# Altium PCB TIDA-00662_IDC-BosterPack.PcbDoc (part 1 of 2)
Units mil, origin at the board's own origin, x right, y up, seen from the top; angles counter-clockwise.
Board outline 2854.33 x 3248.03 mil, 4 copper layers (Top Layer, GND, +3.3V_Supply, Bottom Layer), stack 35.6 mil thick; 124 components, 110 nets, 427 pads, 203 vias.
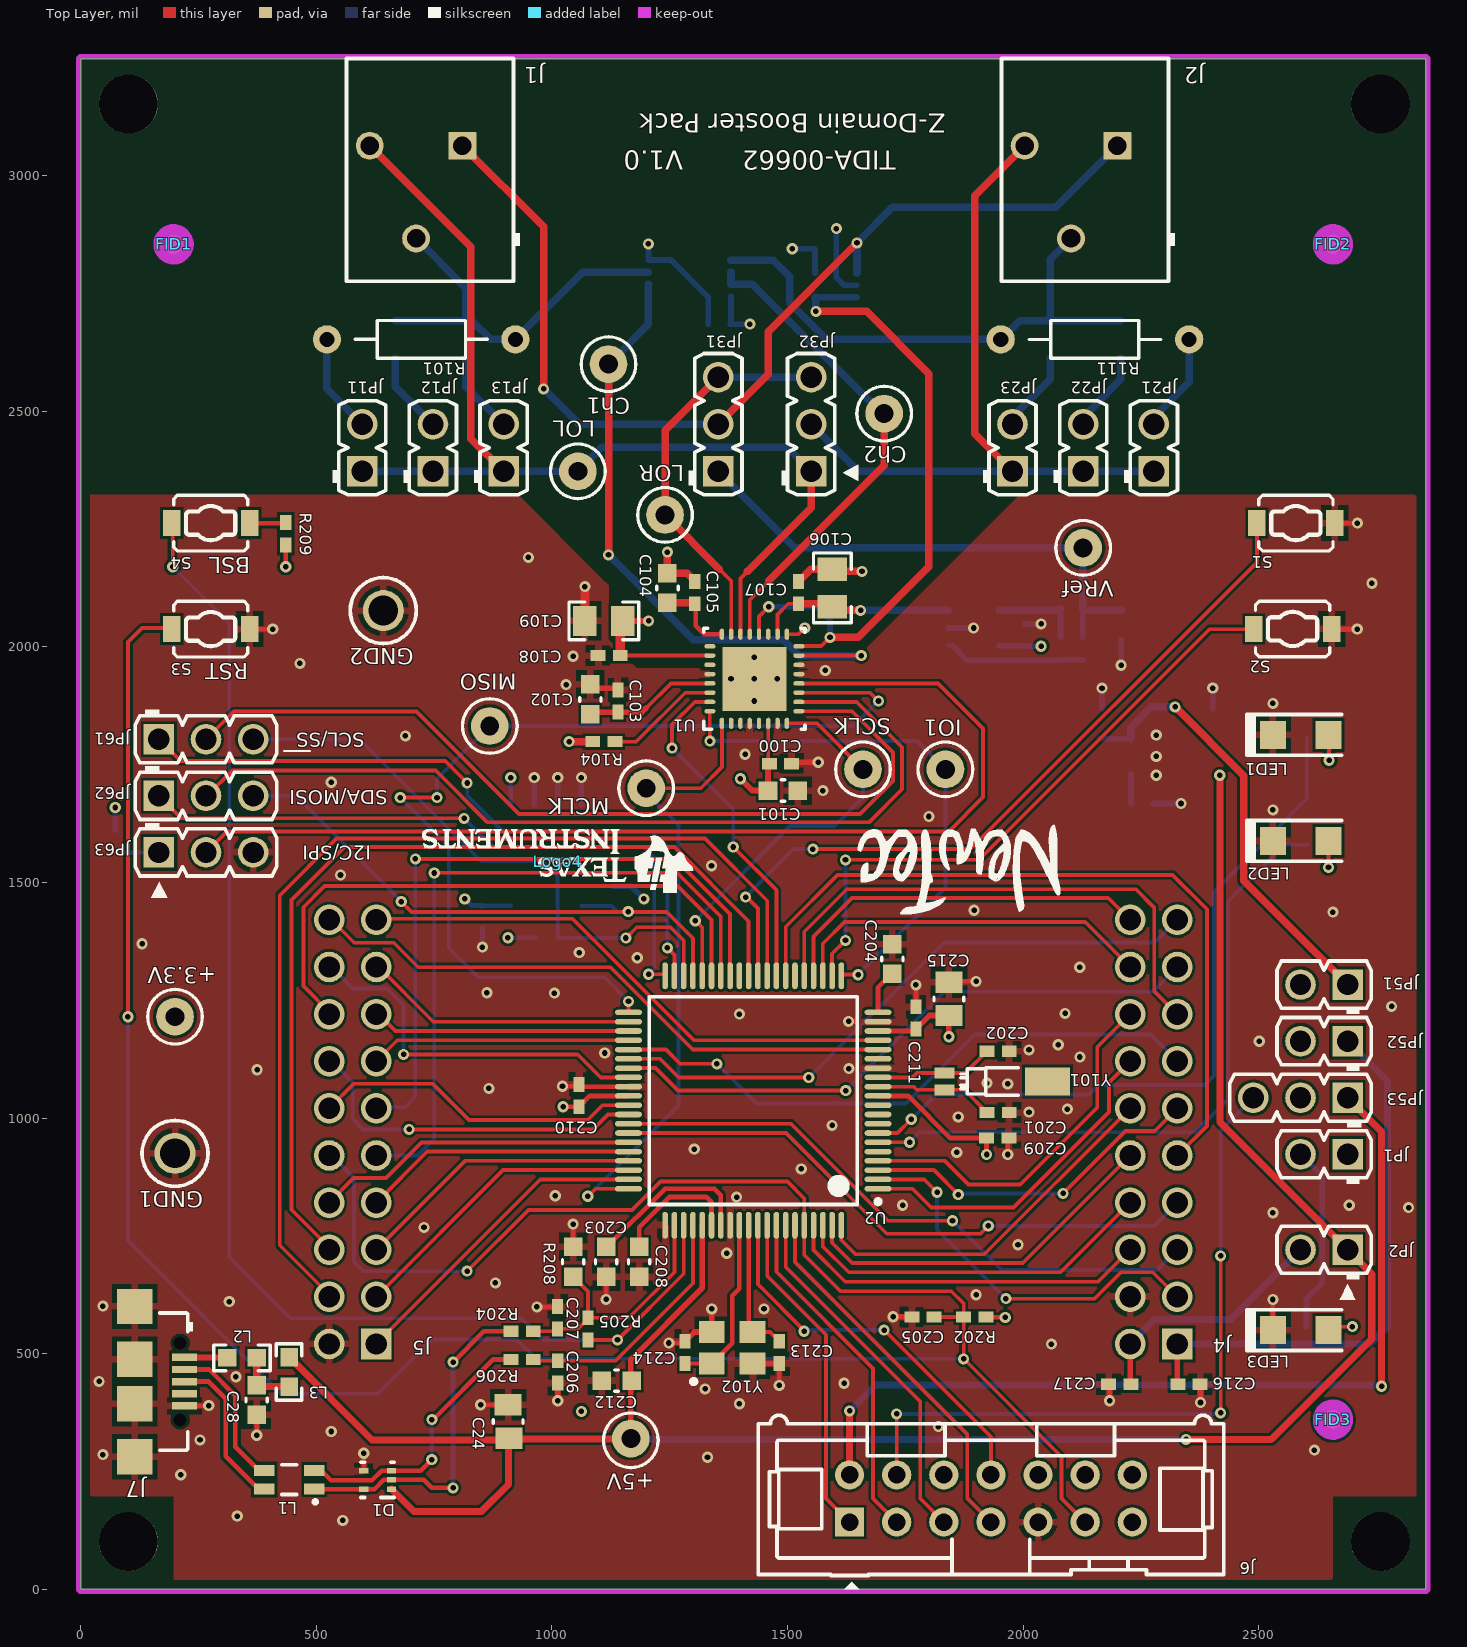
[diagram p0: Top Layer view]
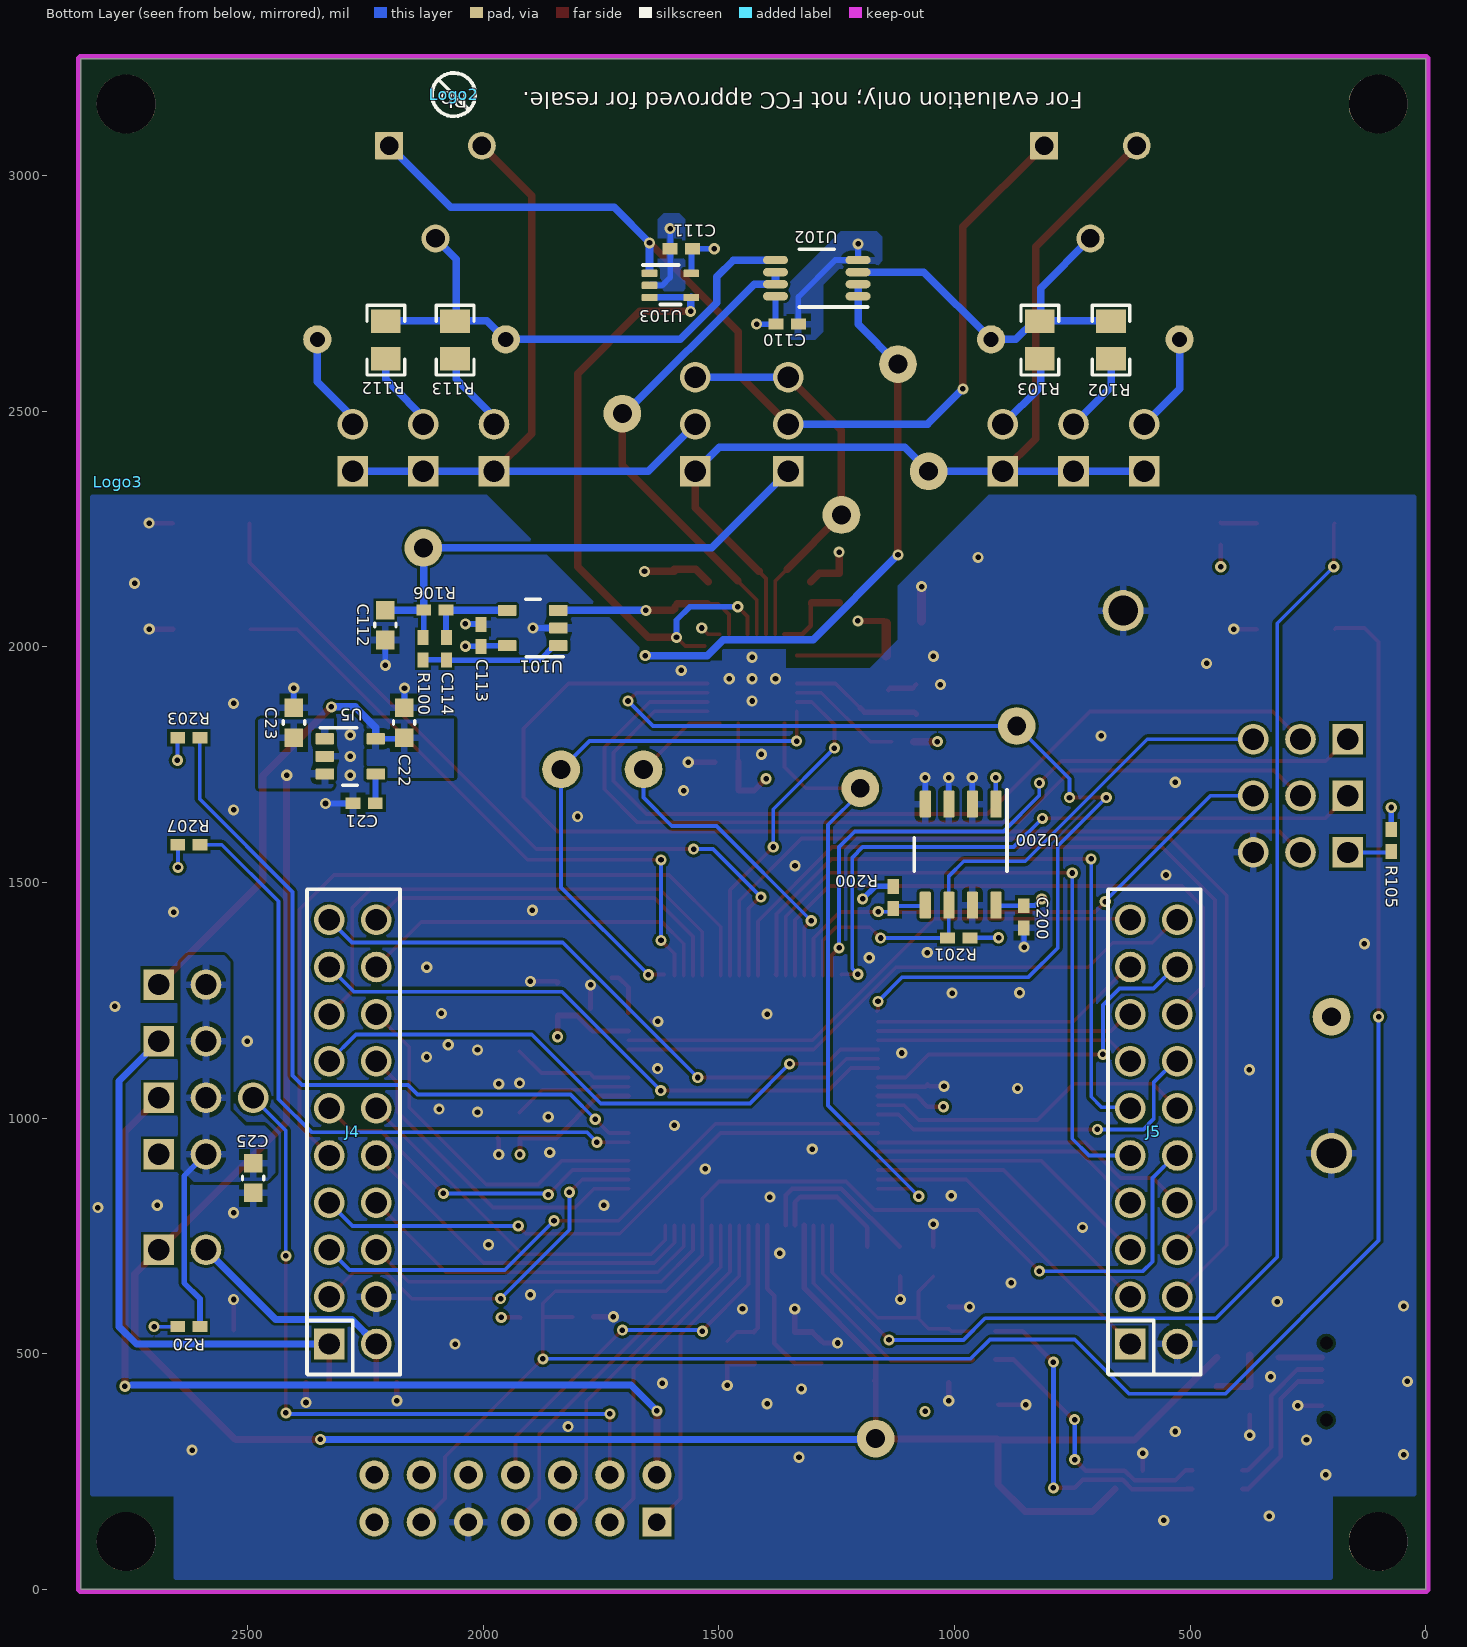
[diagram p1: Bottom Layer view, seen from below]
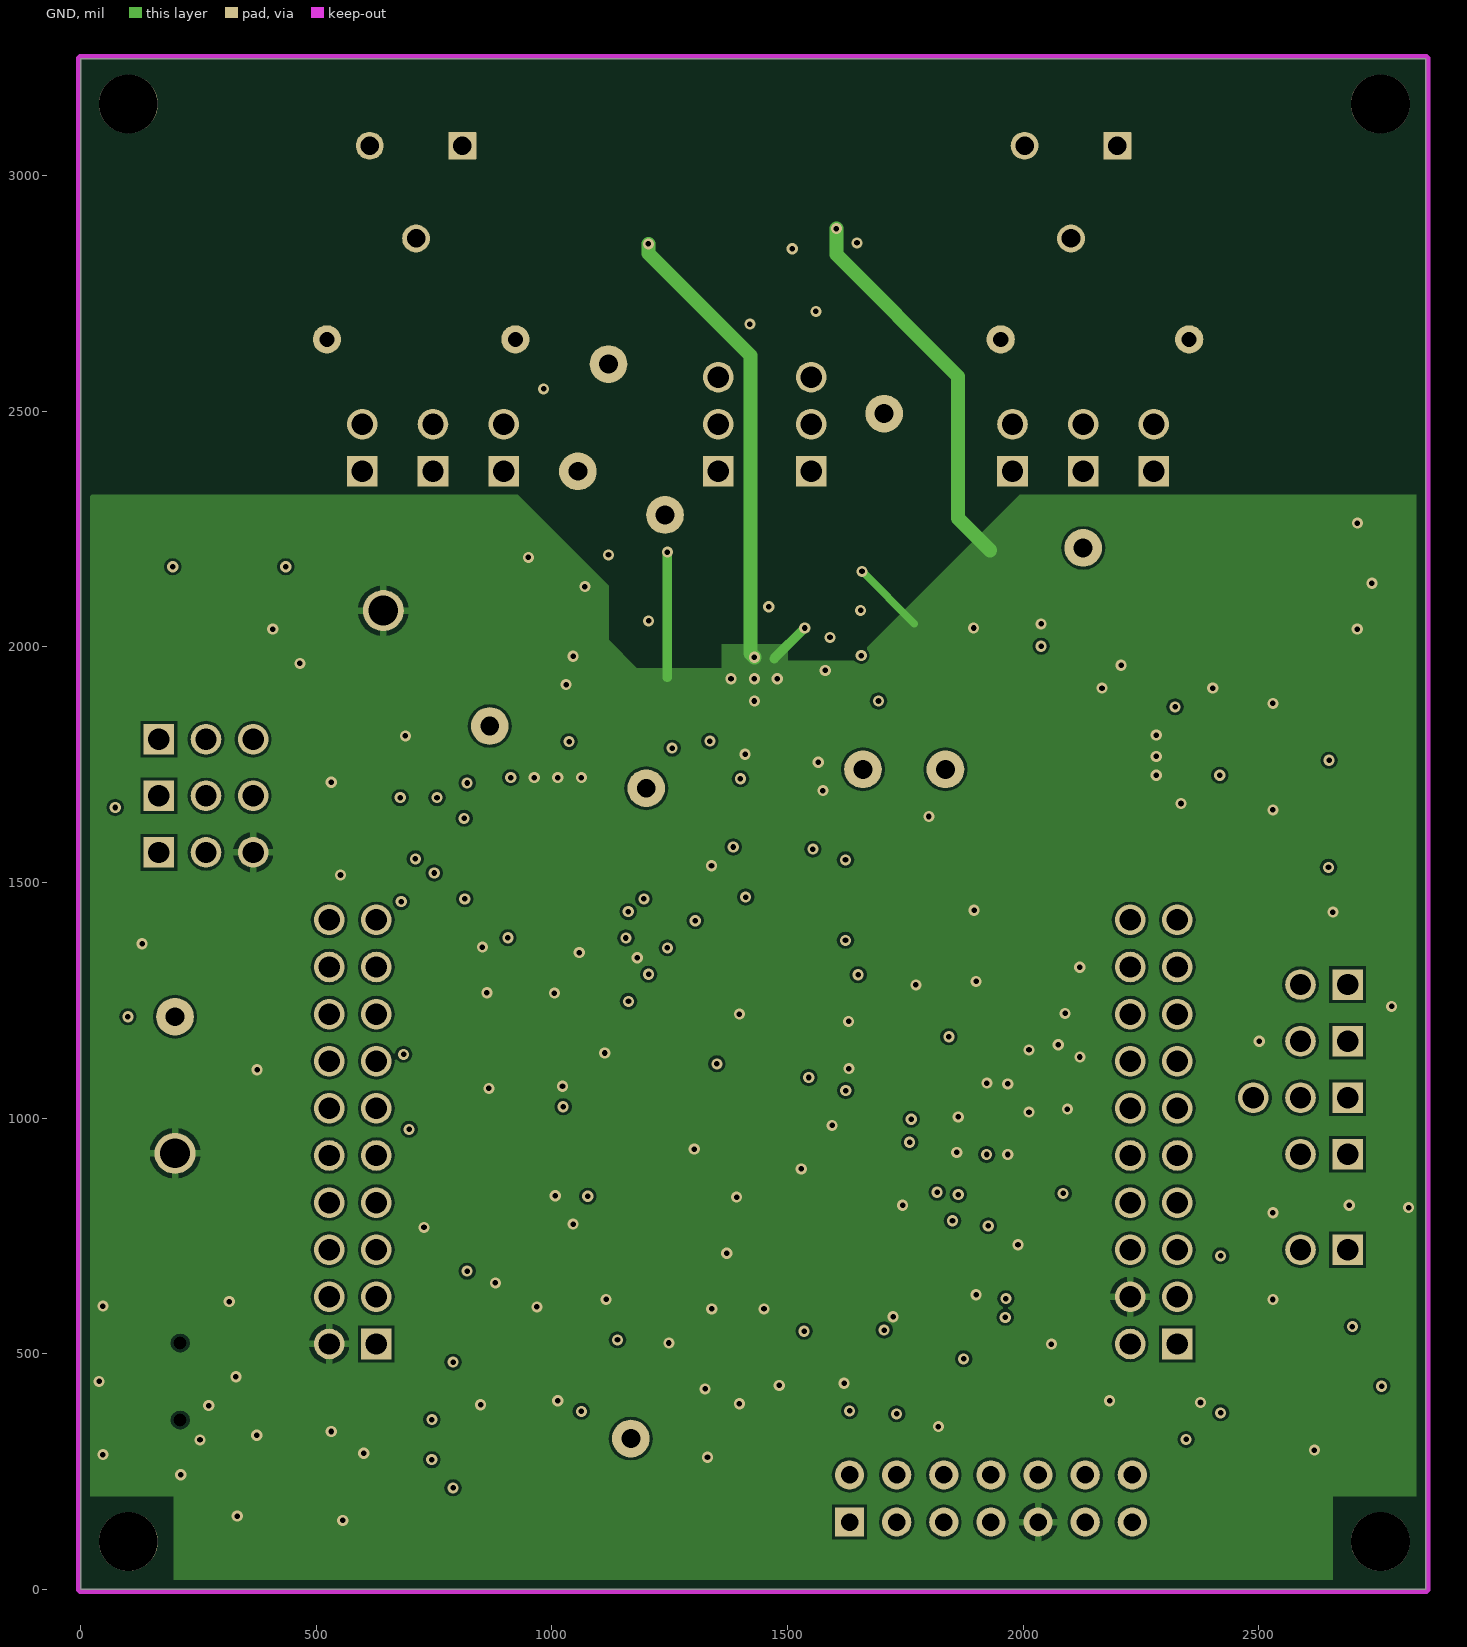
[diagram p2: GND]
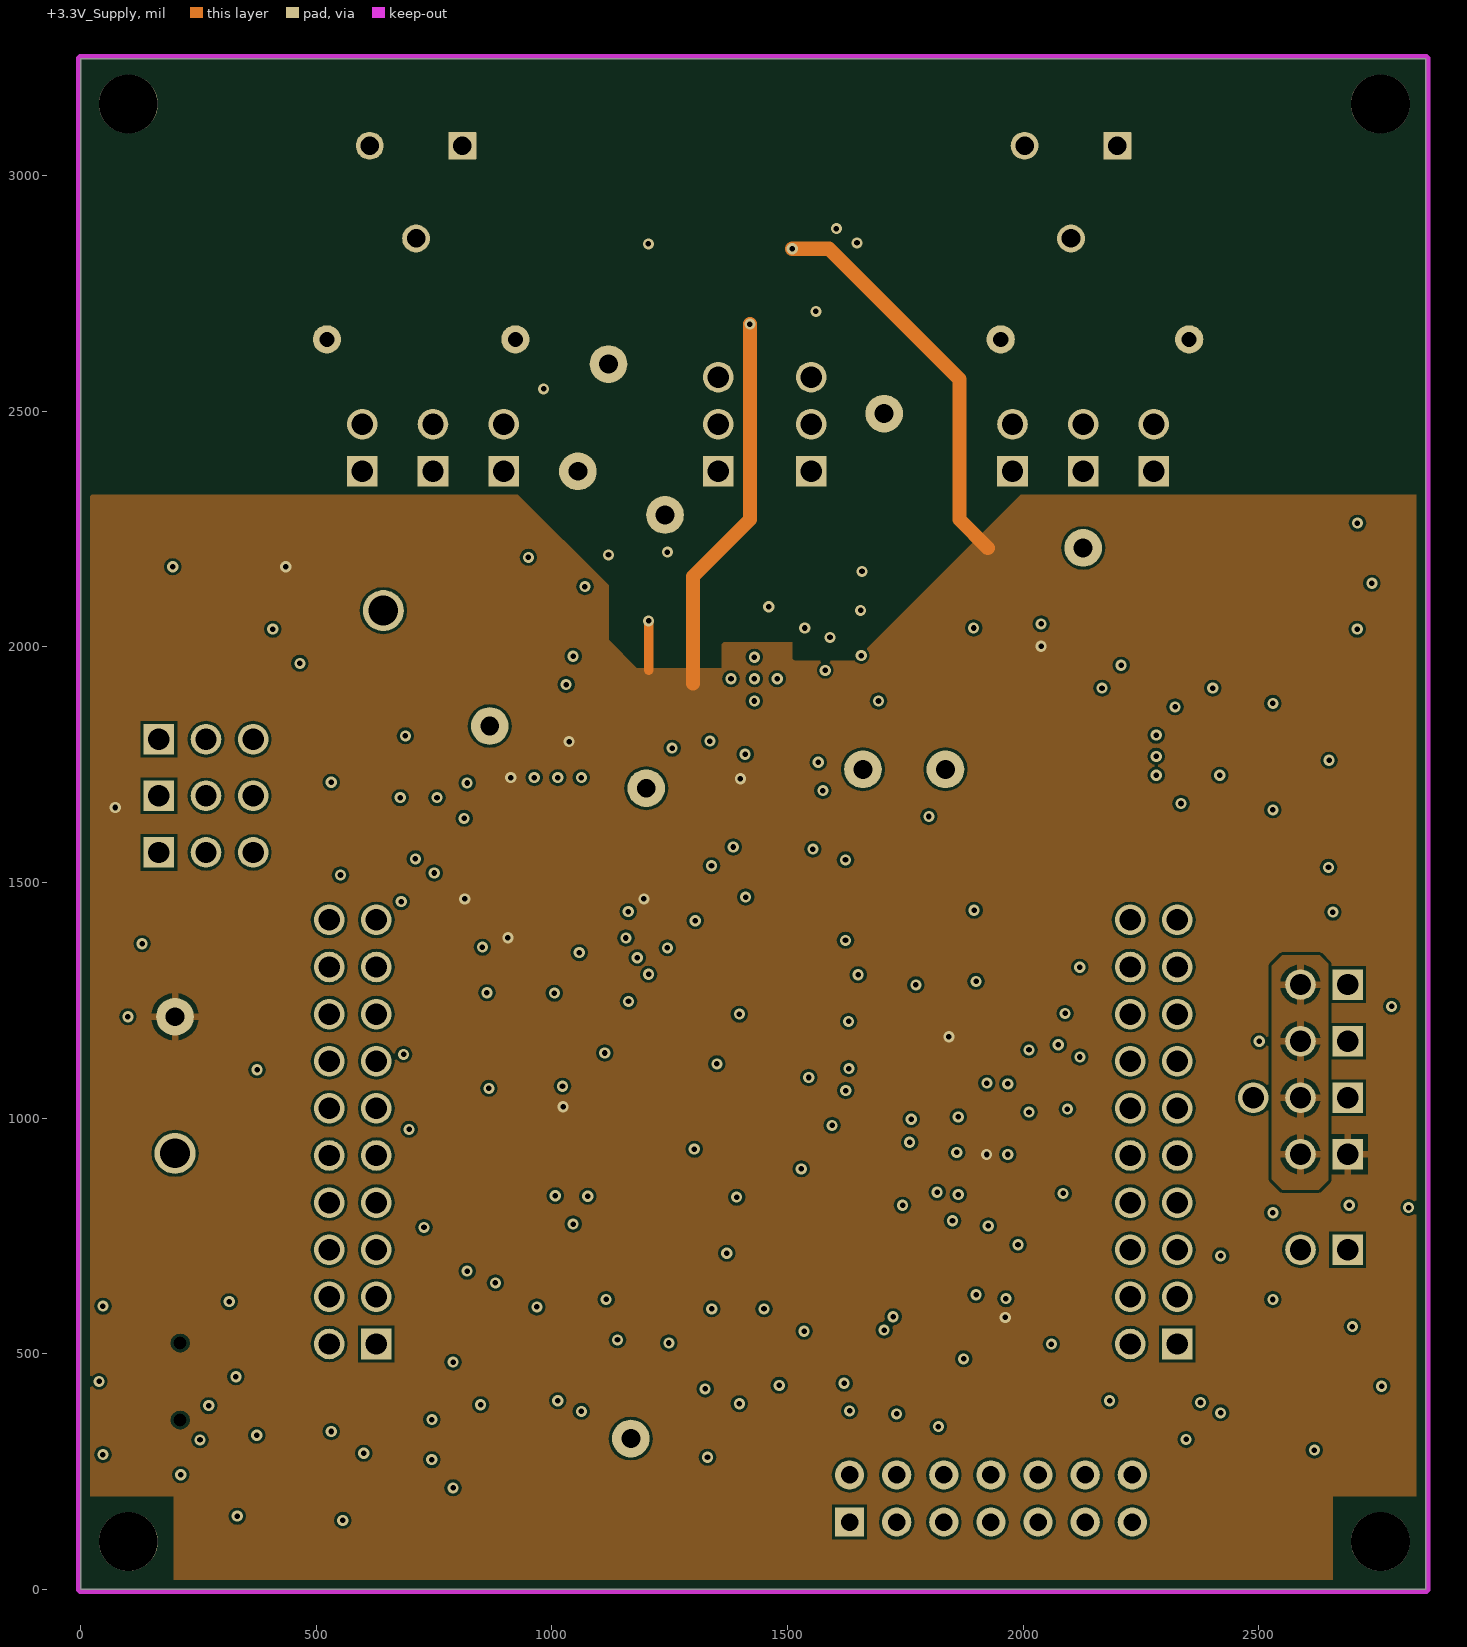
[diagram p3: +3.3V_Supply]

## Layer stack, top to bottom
Top Solder: solder mask 0.4, Solder Resist, Dk 3.5
Top Layer: signal copper 1.4
Dielectric1: prepreg 5, FR-4, Dk 4.2
Dielectric 6: prepreg 5, FR-4, Dk 4.2
GND: signal copper 1.4
Dielectric3: prepreg 5, FR-4, Dk 4.2
Dielectric5: prepreg 5, FR-4, Dk 4.2
+3.3V_Supply: signal copper 1.4
Dielectric4: prepreg 5, FR-4, Dk 4.2
Dielectric 8: prepreg 5, FR-4, Dk 4.2
Bottom Layer: signal copper 1.4
Bottom Solder: solder mask 0.4, Solder Resist, Dk 3.5

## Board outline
0,0 2854.33,0 2854.33,3248.03 0,3248.03

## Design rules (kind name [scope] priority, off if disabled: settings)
Clearance [All] p1: gap=6
DiffPairsRouting [All] p1: maxlimit=393.7 minlimit=4.92 mostfreqgap=5.91 toplayer_minwidth=15 toplayer_maxwidth=15 toplayer_prefwidth=15 midlayer2_minwidth=15 midlayer2_maxwidth=15 midlayer2_prefwidth=15 midlayer3_minwidth=15 midlayer3_maxwidth=15 midlayer3_prefwidth=15 bottomlayer_minwidth=15 bottomlayer_maxwidth=15 bottomlayer_prefwidth=15 maxuncoupledlength=500
FabricationTestPointUsage FabricationTestPointUsage_1 [All] p1: valid=0 allowmultiple=FALSE
FabricationTestpoint FabricationTestpoint_1 [All] p1: side=3 testpointundercomponent=TRUE minsize=40 maxsize=100 preferedsize=60 minholesize=0 maxholesize=40 preferedholesize=32 testpointgrid=1 allowsidetop=TRUE allowsidebottom=TRUE usegrid=TRUE gridtolerance=0.01
HoleSize [All] p1: absolutevalues=TRUE maxlimit=236.22 minlimit=7.87 maxpercent=80.000 minpercent=20.000
HoleSize FabricationTestpoint [All] p2 off: absolutevalues=TRUE maxlimit=100 minlimit=1 maxpercent=80.000 minpercent=20.000
HoleSize FabricationTestPointUsage [All] p3 off: absolutevalues=TRUE maxlimit=100 minlimit=1 maxpercent=80.000 minpercent=20.000
MinimumSolderMaskSliver MinimumSolderMaskSliverTPD2E001 [HasFootprint('DRL0005A') vs HasFootprint('DRL0005A')] p1: minsoldermaskwidth=1.77
MinimumSolderMaskSliver MinimumSolderMaskSliverOPA2376 [HasFootprint('DGK0008A_N') vs HasFootprint('DGK0008A_N')] p2: minsoldermaskwidth=1
MinimumSolderMaskSliver MinimumSolderMaskSliver_MSP [HasFootprint('PN0080A_N') vs HasFootprint('PN0080A_N')] p3: minsoldermaskwidth=1
MinimumSolderMaskSliver [All] p4: minsoldermaskwidth=2
PlaneClearance [All] p1: clearance=19.68
PlaneConnect [All] p1: planeconnectstyle=Relief reliefexpansion=15.75 reliefentries=4 reliefconductorwidth=5.91 reliefairgap=5.91
PolygonConnect ViaConnect [IsVia] p1: connectstyle=Direct reliefconductorwidth=10 reliefentries=4 polygonreliefangle="90 Angle" airgapwidth=10
PolygonConnect [All] p2: connectstyle=Relief reliefconductorwidth=15 reliefentries=4 polygonreliefangle="90 Angle" airgapwidth=10
RoutingCorners [All] p1: cornerstyle=45-Degree minsetback=49.21 maxsetback=49.21
RoutingVias [All] p1: holewidth=11.81 width=23.62 viastyle="Through Hole" minholewidth=3.94 minwidth=9.84 maxholewidth=17.72 maxwidth=29.53
SilkToSilkClearance SilkToSilkClearance_Pb-free [(HasFootprint('Pb-Free_Overlay_Medium') OR HasFootprint('Pb-Free_Overlay_Small')) vs (HasFootprint('Pb-Free_Overlay_Medium') OR HasFootprint('Pb-Free_Overlay_Small'))] p1: silktosilkclearance=0
SilkToSilkClearance [All] p2: silktosilkclearance=3
SilkToSolderMaskClearance [IsPad] p1: minsilkscreentomaskgap=1 clearancetoexposedcopper=FALSE
SolderMaskExpansion [All] p1: expansion=2.95
Width [All] p1: maxlimit=393.7 minlimit=3 preferedwidth=5.91
20 further rules are at their usual default settings.

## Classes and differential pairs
component class AssemblyNote: ZZ2 ZZ3 ZZ4
component class FiducialMark: FID1 FID2 FID3
component class TIDA-00662_TID_Hardware: FID1 FID2 FID3 Logo2 Logo3 Logo4 ZZ2 ZZ3 ZZ4
component class Logo: Logo4
component class Header: J6 JP1 JP2 JP11 JP12 JP13 JP21 JP22 JP23 JP31 JP32 JP51 JP52 JP53 JP61 JP62 JP63
component class TIDA-00662_AIC3254: C100 C101 C102 C103 C104 C105 C106 C107 C108 C109 C110 C111 C112 C113 C114 Ch1 Ch2 IO1 J J1 J2 JP11 JP12 JP13 JP21 JP22 JP23 JP31 JP32 JP61 JP62 JP63 LOL LOR MCLK MISO R100 R101 R102 R103 R104 R105 R106 R111 R112 R113 SCLK U1 U101 U102 U103 VRef
component class TIDA-00662_ExternalInterfaces: C28 C216 C217 D1 J J4 J5 J6 J7 L1 L2 L3
component class TIDA-00662_MCU: C200 C201 C202 C203 C204 C205 C206 C207 C208 C209 C210 C211 C212 C213 C214 C215 LED1 LED2 R200 R201 R202 R203 R204 R205 R206 R207 R208 R209 S1 S2 S3 S4 U2 U200 Y101 Y102
component class TIDA-00662_PowerSupply: +3.3V +5V C21 C22 C23 C24 C25 GND1 GND2 JP1 JP2 JP51 JP52 JP53 LED3 R20 U5

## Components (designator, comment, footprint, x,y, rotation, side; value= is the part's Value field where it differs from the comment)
+3.3V "5000" Keystone5000#1 200,1215 r90 top
+5V "5000" Keystone5000#2 1167.37,316 r90 top
C21 "10nF" 0402W 2253,1668 r0 bottom
C22 "0.1uF" 0603_095 2168,1839 r270 bottom
C23 "0.1uF" 0603_095 2402,1839 r270 bottom
C24 "4.7uF" 0805_145#1 907,356 r90 top
C25 "0.1uF" 0603_095 2488.58,872.5 r90 bottom
C28 "680nF" 0603_095 373.3,401.7 r90 top
C100 "0.1uF" 0402W 1485,1752 r180 top
C101 "1uF" 0603_095 1490,1695 r180 top
C102 "1uF" 0603_095 1081.3,1888.7 r270 top
C103 "0.1uF" 0402W 1140,1885 r270 top
C104 "1uF" 0603_095 1245,2125 r270 top
C105 "0.1uF" 0402W 1302.87,2115 r270 top
C106 "1uF" 0805_HV 1595,2125 r270 top
C107 "0.1uF" 0402W 1523,2115 r90 top
C108 "0.1uF" 0402W 1121.38,1981.5 r0 top
C109 "2.2uF" 0805_HV 1110,2055 r180 top
C110 "0.1uF" 0402W 1355,2685 r180 bottom
C111 "0.1uF" 0402W 1580,2845 r0 bottom
C112 "1uF" 0603_095 2208,2046 r90 bottom
C113 "0.1uF" 0402W 2005,2024 r90 bottom
C114 "47nF" 0402W 2078,1996 r270 bottom
C200 "0.1uF" 0402W 853,1427 r90 bottom
C201 "15pF" 0402W 1946.74,1011.58 r0 top
C202 "15pF" 0402W 1946.74,1141.58 r0 top
C203 "0.22uF" 0603_095 1115,695 r90 top
C204 "470nF" 0603_095 1722.37,1337.52 r270 top
C205 "2200pF" 0402W 1787.37,577.52 r180 top
C206 "10pF" 0402W 1012.37,461.14 r270 top
C207 "10pF" 0402W 1011.58,576.14 r90 top
C208 "0.22uF" 0603_095 1185,695 r90 top
C209 "0.1uF" 0402W 1945.99,957.52 r0 top
C210 "0.1uF" 0402W 1057.37,1047.52 r90 top
C211 "0.1uF" 0402W 1772.37,1212.52 r90 top
C212 "0.22uF" 0603_095 1137.37,442.52 r0 top
C213 "33pF" 0402W 1482.37,502.52 r270 top
C214 "33pF" 0402W 1282.37,502.52 r270 top
C215 "4.7uF" 0805_145#2 1842.37,1252.95 r90 top
C216 "0.1uF" 0402W 2352,435 r180 top
C217 "0.1uF" 0402W 2205,435 r0 top
Ch1 "5002" Keystone5002 1120,2600 r90 top
Ch2 "5002" Keystone5002 1705,2495 r90 top
D1 "TPD2E001DRLR" DRL0005A 630,232 r180 top
FID1 "Fiducial" Fiducial10-20 196.85,2854.33 r90 top
FID2 "Fiducial" Fiducial10-20 2657.48,2854.33 r90 top
FID3 "Fiducial" Fiducial10-20 2657.48,360 r90 top
GND1 "5011" Keystone5011 200,925 r90 top
GND2 "5011" Keystone5011 642,2077 r90 top
IO1 "5002" Keystone5002 1835,1740 r90 top
J1 "1990012" Phoenix_1990012 711.58,2965.16 r180 top
J2 "1990012" Phoenix_1990012 2101.57,2965.16 r180 top
J4 "SSW-110-23-F-D" CONN_SSW-110-23-F-D 2277.17,970.47 r270 bottom
J5 "SSW-110-23-F-D" CONN_SSW-110-23-F-D 577.17,970.47 r270 bottom
J6 "N2514-6002-RB" 3M_x2514-60xx 1931.58,192.52 r0 top
J7 "629105136821" Wurth_629105136821 57.46,440.69 r270 top
JP1 "61300211121" WURTH_61300211121 2638.58,922.99 r180 top
JP2 "61300211121" WURTH_61300211121 2638.58,720.47 r180 top
JP11 "61300211121" WURTH_61300211121 597.37,2422.52 r90 top
JP12 "61300211121" WURTH_61300211121 747.37,2422.52 r90 top
JP13 "61300211121" WURTH_61300211121 897.37,2422.52 r90 top
JP21 "61300211121" WURTH_61300211121 2277.37,2422.52 r90 top
JP22 "61300211121" WURTH_61300211121 2127.37,2422.52 r90 top
JP23 "61300211121" WURTH_61300211121 1977.37,2422.52 r90 top
JP31 "61300311121" WURTH_61300311121 1353.16,2472.52 r90 top
JP32 "61300311121" WURTH_61300311121 1550.01,2472.52 r90 top
JP51 "61300211121" WURTH_61300211121 2638.58,1283.23 r180 top
JP52 "61300211121" WURTH_61300211121 2638.58,1163.15 r180 top
JP53 "61300311121" WURTH_61300311121 2588.58,1043.07 r180 top
JP61 "61300311121" WURTH_61300311121 265.75,1803.86 r0 top
JP62 "61300311121" WURTH_61300311121 265.75,1683.78 r0 top
JP63 "61300311121" WURTH_61300311121 265.75,1563.7 r0 top
L1 "744232090" WE-CNSW_1206 442.37,232.52 r180 top
L2 "742792651" 0603 342,491 r0 top
L3 "742792651" 0603 442,461 r90 top
LED1 "150120RS75000" WL_SMCW_RED_1206 2588.94,1813 r0 top
LED2 "150120RS75000" WL_SMCW_RED_1206 2588.94,1588 r0 top
LED3 "150120RS75000" WL_SMCW_RED_1206 2588.95,550 r0 top
Logo2 "Pb-Free Symbol" Pb-Free_Overlay_Small 2063,3172 r0 bottom
Logo3 "FCC disclaimer" FCC_disclaimer 2776.01,2349 r270 bottom
Logo4 "Texas Instruments" TI_Stacked_Overlay_Small_Vertical 1012,1544 r90 top
LOL "5002" Keystone5002 1055,2372.52 r90 top
LOR "5002" Keystone5002 1240,2280 r90 top
MCLK "5002" Keystone5002 1200,1700 r90 top
MISO "5002" Keystone5002 868,1832 r90 top
R20 "1.00k" 0402W 2625,557.19 r0 bottom
R100 "51" 0402W 2128,1996 r270 bottom
R101 "150k" CMF50 722.37,2652.52 r180 top
R102 "100k" 0805_HV 668,2651 r270 bottom
R103 "200k" 0805_HV 819,2651 r270 bottom
R104 "4.7k" 0402W 1110,1798.79 r0 top
R105 "4.7k" 0402W 73,1589 r270 bottom
R106 "2.00k" 0402W 2103,2078 r180 bottom
R111 "150k" CMF50 2152.37,2652.52 r0 top
R112 "100k" 0805_HV 2207,2651 r270 bottom
R113 "200k" 0805_HV 2060,2651 r270 bottom
R200 "2.7k" 0402W 1130,1468 r90 bottom
R201 "2.7k" 0402W 991,1382 r180 bottom
R202 "47k" 0402W 1897.37,577.52 r0 top
R203 "1.00k" 0402W 2625,1807 r180 bottom
R204 "27" 0402W 936.58,547.52 r180 top
R205 "1.40k" 0402W 1076.58,552.52 r90 top
R206 "27" 0402W 936.58,487.52 r180 top
R207 "1.00k" 0402W 2625,1580 r180 bottom
R208 "1.00Meg" 0603_095 1045,695 r270 top
R209 "100" 0402W 435,2240 r270 top
S1 "TL1015AF160QG" SW_TL1015AF160QG 2578.74,2262.52 r0 top
S2 "TL1015AF160QG" SW_TL1015AF160QG 2572,2038 r180 top
S3 "RST" SW_TL1015AF160QG 275.59,2037.52 r0 top
S4 "BSL" SW_TL1015AF160QG 275.59,2262.52 r0 top
SCLK "5002" Keystone5002 1660,1740 r90 top
U1 "TLV320AIC3254IRHB" RHB0032E_NV 1429.54,1932.28 r90 top
U2 "MSP430F5529IPN" PN0080A_N 1427.17,1037.05 r180 top
U5 "TPS73633DBV" DBV0005A_N 2282.37,1767.52 r180 bottom
U101 "OPA317IDBV" DBV0005A_N 1895,2040 r0 bottom
U102 "OPA2376AIDGKR" DGK0008A_N 1292.37,2782.52 r0 bottom
U103 "OPA376AIDCKR" DCK0005A_N 1603,2767 r180 bottom
U200 "24FC1025T-I/SN" SOIC-8 987,1559 r270 bottom
VRef "5002" Keystone5002 2127.37,2210 r90 top
Y101 "MS3V-T1R 32.768KHZ +/-20PPM 12.5PF" XTAL_MS3V-T1R 1942.41,1077.56 r0 top
Y102 "7M-12.000MAAJ-T" TXC_7M 1382.37,512.52 r90 top
ZZ2 "These assemblies are ESD sensitive, ESD precautions shall be observed." AssemblyNote 185,3829.11 r0 top
ZZ3 "These assemblies must be clean and free from flux and all contaminants. Use of no clean flux is not acceptable." AssemblyNote 185,3740.56 r0 top
ZZ4 "These assemblies must comply with workmanship standards IPC-A-610 Class 2, unless otherwise specified." AssemblyNote 185,3652 r0 top

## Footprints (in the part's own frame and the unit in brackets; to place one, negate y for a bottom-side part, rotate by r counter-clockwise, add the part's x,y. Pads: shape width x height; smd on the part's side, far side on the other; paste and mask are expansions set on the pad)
3M_x2514-60xx [mil] "3M"
  rect 62x62 hole 37 paste+2: 1(-300,-50)
  round 62 hole 37: 2(-300,50) 3(-200,-50) 4(-200,50) 5(-100,-50) 6(-100,50) 7(0,-50) 8(0,50) 9(100,-50) 10(100,50) 11(200,-50) 12(200,50) 13(300,-50) 14(300,50)
  silkscreen extent -494,-193 494,177, body extent -494,-161 494,179, height 390
0402W [mm] "without printed body shape"
  rect 0.8x0.6 smd: 1(-0.6,0) 2(0.6,0)
  body extent -0.55,-0.3 0.55,0.3, height 0.6
0603 [mm] "0603 from SM-752 data"
  rect 1x0.95 smd: 1(-0.8,0) 2(0.8,0)
  silkscreen extent -1.52,-0.69 1.52,0.69, body extent -0.87,-0.47 0.87,0.47, height 1
0603_095 [mm] "0603_095"
  rect 1x1 smd: 1(-0.8,0) 2(0.8,0)
  silkscreen extent -0.1,-0.58 0.1,0.58, body extent -0.87,-0.48 0.87,0.48, height 0.95
0805_145#1 [mm] "0805 / 1.45mm height"
  rect 1.15x1.45 smd: 1(-0.9,-0.052) 2(0.9,0)
  silkscreen extent -0.1,-0.8 0.1,0.8, body extent -1.1,-0.72 1.1,0.72, height 1.45
0805_145#2 [mm] "0805 / 1.45mm height"
  rect 1.15x1.45 smd: 1(-0.9,0) 2(0.9,0)
  silkscreen extent -0.1,-0.8 0.1,0.8, body extent -1.1,-0.72 1.1,0.72, height 1.45
0805_HV [mil] "0805 with 30mil clearance between pads"
  rect 50x63 smd: 1(-40,0) 2(40,0)
  silkscreen extent -74,-40 74,40, body extent -43,-29 43,29, height 57
AssemblyNote [mil] "Assembly Note"
CMF50 [mil] "VIshay Metal Film Resistors 1/4W"
  round 60 hole 32: 1(-200,0) 2(200,0)
  silkscreen extent -140,-40 140,40, body extent -214,-40 214,40, height 80
CONN_SSW-110-23-F-D [mm] "SAMTEC"
  rect 1.65x1.65 hole 1.15: 1(11.43,-1.27)
  round 1.65 hole 1.15: 2(11.43,1.27) 3(8.89,-1.27) 4(8.89,1.27) 5(6.35,-1.27) 6(6.35,1.27) 7(3.81,-1.27) 8(3.81,1.27) 9(1.27,-1.27) 10(1.27,1.27) 11(-1.27,-1.27) 12(-1.27,1.27) 13(-3.81,-1.27) 14(-3.81,1.27) 15(-6.35,-1.27) 16(-6.35,1.27) 17(-8.89,-1.27) 18(-8.89,1.27) 19(-11.43,-1.27) 20(-11.43,1.27)
  silkscreen extent -13.08,-2.46 13.08,2.54, body extent -13,-2.51 13,2.54, height 8.59
DBV0005A_N [mm] "SOT23, 5-Leads, Body 2.9x1.6mm, Pitch 0.95mm, Lead Span 2.8mm, IPC Medium Density"
  rrect17% 1x0.6 smd: 1(-1.375,0.95) 2(-1.375,0) 3(-1.375,-0.95) 4(1.375,-0.95) 5(1.375,0.95)
  silkscreen extent -1.63,-1.55 0.38,1.55, body extent -1.42,-1.46 1.42,1.46, height 1.09
DCK0005A_N [mm] "SOT353, 5-Leads, Body 2x1.3mm, Pitch 0.65mm, Lead Span 2.1mm, IPC Medium Density"
  rrect25% 0.85x0.4 smd: 1(-1.125,0.65) 2(-1.125,0) 3(-1.125,-0.65) 4(1.125,-0.65) 5(1.125,0.65)
  silkscreen extent -1.48,-1.02 0.55,1.1, body extent -1.14,-1 1.14,1, height 0.95
DGK0008A_N [mm] "TSOP, 8-Leads, Body 3x3mm, Pitch 0.65mm, IPC Medium Density"
  oval 1.35x0.45 smd: 1(-2.225,0.975) 2(-2.225,0.325) 3(-2.225,-0.325) 4(-2.225,-0.975) 5(2.225,-0.975) 6(2.225,-0.325) 7(2.225,0.325) 8(2.225,0.975)
  silkscreen extent -2.75,-1.55 0.95,1.55, body extent -2.45,-1.5 2.45,1.5, height 0.96
DRL0005A [mm] "SOTFL, 5-Flat Leads, Body 1.2x1.6x0.6mm, Pitch 0.5mm, TI recommended"
  rect 0.5x0.3 smd: 1(-0.75,0.5) 2(-0.75,0) 3(-0.75,-0.5) 4(0.75,-0.5) 5(0.75,0.5)
  silkscreen extent -0.9,-0.95 0.9,0.95, body extent -0.85,-0.85 0.85,0.85, height 0.62
FCC_disclaimer [mil]
Fiducial10-20 [mm]
  round 1 smd mask+0.5: 1(0,0)
  Top Layer keep-out circle w1.178: c0,0 r0.5
Keystone5000#1 [mil] "For Keystone 500x miniature loop terminals"
  round 80 hole 40: 1(0,0)
  silkscreen extent -58,-58 58,58, body extent -49,-49 49,49, height 182
Keystone5000#2 [mil] "For Keystone 500x miniature loop terminals"
  round 80 hole 40: 1(3.62,0)
  silkscreen extent -58,-58 58,58, body extent -49,-49 49,49, height 182
Keystone5002 [mil] "For Keystone 500x miniature loop terminals"
  round 80 hole 40: 1(0,0)
  silkscreen extent -58,-58 58,58, body extent -49,-49 49,49, height 182
Keystone5011 [mil] "Keystone Multipurpose loops"
  round 87 hole 63: 1(0,0)
  silkscreen extent -70,-70 70,70, body extent -63,-63 63,62, height 319
Pb-Free_Overlay_Small [mil]
  silkscreen extent -46,-46 46,46
Phoenix_1990012 [mm] "Terminal Block, 2.5mm, 3 Pos, TH"
  rrect7% 1.5x1.5 hole 1: 1(-2.5,-2.5)
  round 1.5 hole 1: 2(0,2.5) 3(2.5,-2.5)
  silkscreen extent -5.6,-7.2 3.75,4.8, body extent -5.25,-7.2 3.75,4.8, height 13.11
PN0080A_N [mm] "QFP, 80-Leads, Body 12x12mm, Pitch 0.5mm, IPC Medium Density"
  oval 1.45x0.3 smd: 1(-6.725,4.75) 2(-6.725,4.25) 3(-6.725,3.75) 4(-6.725,3.25) 5(-6.725,2.75) 6(-6.725,2.25) 7(-6.725,1.75) 8(-6.725,1.25) 9(-6.725,0.75) 10(-6.725,0.25) 11(-6.725,-0.25) 12(-6.725,-0.75) 13(-6.725,-1.25) 14(-6.725,-1.75) 15(-6.725,-2.25) 16(-6.725,-2.75) 17(-6.725,-3.25) 18(-6.725,-3.75) 19(-6.725,-4.25) 20(-6.725,-4.75) 41(6.725,-4.75) 42(6.725,-4.25) 43(6.725,-3.75) 44(6.725,-3.25) 45(6.725,-2.75) 46(6.725,-2.25) 47(6.725,-1.75) 48(6.725,-1.25) 49(6.725,-0.75) 50(6.725,-0.25) 51(6.725,0.25) 52(6.725,0.75) 53(6.725,1.25) 54(6.725,1.75) 55(6.725,2.25) 56(6.725,2.75) 57(6.725,3.25) 58(6.725,3.75) 59(6.725,4.25) 60(6.725,4.75)
  oval 0.3x1.45 smd: 21(-4.75,-6.725) 22(-4.25,-6.725) 23(-3.75,-6.725) 24(-3.25,-6.725) 25(-2.75,-6.725) 26(-2.25,-6.725) 27(-1.75,-6.725) 28(-1.25,-6.725) 29(-0.75,-6.725) 30(-0.25,-6.725) 31(0.25,-6.725) 32(0.75,-6.725) 33(1.25,-6.725) 34(1.75,-6.725) 35(2.25,-6.725) 36(2.75,-6.725) 37(3.25,-6.725) 38(3.75,-6.725) 39(4.25,-6.725) 40(4.75,-6.725) 61(4.75,6.725) 62(4.25,6.725) 63(3.75,6.725) 64(3.25,6.725) 65(2.75,6.725) 66(2.25,6.725) 67(1.75,6.725) 68(1.25,6.725) 69(0.75,6.725) 70(0.25,6.725) 71(-0.25,6.725) 72(-0.75,6.725) 73(-1.25,6.725) 74(-1.75,6.725) 75(-2.25,6.725) 76(-2.75,6.725) 77(-3.25,6.725) 78(-3.75,6.725) 79(-4.25,6.725) 80(-4.75,6.725)
  silkscreen extent -6.85,-5.6 5.6,5.6, body extent -7,-7 7,7, height 1.56
RHB0032E_NV [mm] "QFN, 32-Leads, Body 5x5mm, Pitch 0.5mm, Thermal Pad 3.45x3.45mm, TI Recommended"
  oval 0.6x0.24 smd: 1(-2.4,1.75) 2(-2.4,1.25) 3(-2.4,0.75) 4(-2.4,0.25) 5(-2.4,-0.25) 6(-2.4,-0.75) 7(-2.4,-1.25) 8(-2.4,-1.75) 17(2.4,-1.75) 18(2.4,-1.25) 19(2.4,-0.75) 20(2.4,-0.25) 21(2.4,0.25) 22(2.4,0.75) 23(2.4,1.25) 24(2.4,1.75)
  oval 0.24x0.6 smd: 9(-1.75,-2.4) 10(-1.25,-2.4) 11(-0.75,-2.4) 12(-0.25,-2.4) 13(0.25,-2.4) 14(0.75,-2.4) 15(1.25,-2.4) 16(1.75,-2.4) 25(1.75,2.4) 26(1.25,2.4) 27(0.75,2.4) 28(0.25,2.4) 29(-0.25,2.4) 30(-0.75,2.4) 31(-1.25,2.4) 32(-1.75,2.4)
  rect 3.45x3.45 smd paste-1.725: 33(0,0)
  silkscreen extent -2.72,-2.73 2.72,2.73, body extent -2.57,-2.57 2.58,2.58, height 1.01
SOIC-8 [mm] "duplicate of SO-8.  SOIC, 8-Leads, Body 5.0x4.0mm (max), Pitch 1.27mm, IPC Medium Density"
  rrect17% 1.45x0.6 smd: 1(-2.725,1.905) 2(-2.725,0.635) 3(-2.725,-0.635) 4(-2.725,-1.905) 5(2.725,-1.905) 6(2.725,-0.635) 7(2.725,0.635) 8(2.725,1.905)
  silkscreen extent -3.5,-2.5 0.9,2.5, body extent -3,-2.45 3,2.45, height 1.63
SW_TL1015AF160QG [mm] "E-Switch"
  rect 0.95x1.4 smd: 1(-2.1,0) 2(2.1,0)
  silkscreen extent -2,-1.5 2,1.5, body extent -2.3,-1.5 2.3,1.5, height 2
TI_Stacked_Overlay_Small_Vertical [mil]
  silkscreen extent -66,-288 69,288
TXC_7M [mm] "TXC"
  rect 1.2x1.4 smd: 1(-0.85,1.1) 2(-0.85,-1.1) 3(0.85,-1.1) 4(0.85,1.1)
  silkscreen extent -1.95,1.95 -1.7,2.2, body extent -1.3,-1.65 1.3,1.65, height 0.8
WE-CNSW_1206 [mm] "SMD, 4-Leads, Body 3.2x1.6mm"
  rect 1.1x0.6 smd: 1(-1.35,0.5) 2(1.35,0.5) 3(1.35,-0.5) 4(-1.35,-0.5)
  silkscreen extent -1.5,-0.8 0.4,1.3, body extent -1.6,-0.8 1.6,0.8, height 1.91
WL_SMCW_RED_1206 [mm] "SMD, 2-Leads, Body 3.2x1.6mm, Pitch 3mm"
  rect 1.4x1.5 smd: 1(-1.5,0) 2(1.5,0)
  silkscreen extent -2.9,-1.1 2.2,1.1, body extent -1.6,-0.85 1.6,0.85, height 0.78
WURTH_61300211121 [mm] "Header, 2.54mm, 2x1, TH"
  rect 1.65x1.65 hole 1.15: 1(-1.27,0)
  round 1.65 hole 1.15: 2(1.27,0)
  silkscreen extent -2.54,-1.27 2.54,1.6, body extent -2.54,-1.27 2.54,1.27, height 8.54
WURTH_61300311121 [mm] "Header, 2.54mm, 3x1, TH"
  rect 1.65x1.65 hole 1.15: 1(-2.54,0)
  round 1.65 hole 1.15: 2(0,0) 3(2.54,0)
  silkscreen extent -3.81,-1.27 3.81,1.6, body extent -3.81,-1.27 3.81,1.27, height 8.54
Wurth_629105136821 [mm] "USB 2.0 TYPE B, R/A, SMT"
  rect 0.4x1.35 smd: 1(-1.3,4.125) 2(-0.65,4.125) 3(0,4.125) 4(0.65,4.125) 5(1.3,4.125)
  rect 1.9x1.9 smd: 6(-4.05,1.45) 7(-1.2,1.45) 8(1.2,1.45) 9(4.05,1.45)
  round 0 hole 0.7 unplated: MH1(-2.075,3.9) MH2(2.075,3.9)
  silkscreen extent -3.7,2.8 3.7,4.6, body extent -4,-1.3 4,4.6, height 2.7
XTAL_MS3V-T1R [mm] "Micro Crystal Switzerland recommended land pattern"
  rect 1.1x0.6 smd: 1(-2.775,0.45) 2(-2.775,-0.45)
  rect 2.4x1.5 smd: ""(2.775,0)
  silkscreen extent -1.9,-0.74 1.2,0.74, body extent -3.05,-0.74 3.65,0.74, height 1.42

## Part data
+3.3V +5V: "Test Point, Miniature, Red, TH"
C21: library part 885012205031, "CAP, CERM, 0.01 µF, 16 V, +/- 10%, X7R, 0402"
C22 C23 C25: library part 885012206046, "CAP, CERM, 0.1 µF, 16 V, +/- 10%, X7R, 0603_095"
C24 C215: library part 885012207025, "CAP, CERM, 4.7 µF, 10 V, +/- 10%, X7R, 0805"
C28: library part 885012206051, "CAP, CERM, 680 nF, 16V, +/- 10%, X7R, 0603_095"
C100 C103 C105 C107 C108 C110 C111 C113 C200 C209 C210 C211 C216 C217: library part 885012205037, "CAP, CERM, 0.1 µF, 16 V, +/- 10%, X7R, 0402"
C101 C102 C104 C112: library part 885012206052, "CAP, CERM, 1 µF, 16 V, +/- 10%, X7R, 0603_095"
C106: library part 08055C105KAT2A, "CAP, CERM, 1 µF, 50 V, +/- 10%, X7R, 0805"
C109: library part 0805YD225KAT2A, "CAP, CERM, 2.2 µF, 16 V, +/- 10%, X5R, 0805"
C114: library part 885012205035, "CAP, CERM, 47 nF, 16 V, +/- 10%, X7R 0402"
C201 C202: library part 885012005056, "CAP, CERM, 15 pF, 50 V, +/- 5%, C0G/NP0, 0402"
C203 C208 C212: library part 885012206048, "CAP, CERM, 0.22 µF, 16 V, +/- 10%, X7R, 0603_095"
C204: library part 885012206050, "CAP, CERM, 470 nF, 16 V, +/- 10%, X7R, 0603_095"
C205: library part 885012205027, "CAP, CERM, 2200 pF, 16 V, +/- 10%, X7R, 0402"
C206 C207: library part 885012005025, "CAP, CERM, 10 pF, 16 V, +/- 5%, C0G/NP0, 0402"
C213 C214: library part 885012005043, "CAP, CERM, 33 pF, 25 V, +/- 5%, C0G/NP0, 0402"
Ch1 Ch2 IO1 LOL LOR MCLK MISO SCLK VRef: "Test Point, Miniature, White, TH"
D1: "Low-Capacitance + / - 15 kV ESD-Protection Array for High-Speed Data Interfaces, 2 Channels, -40 to +85 degC, 5-pin SOT (DRL), Green (RoHS & no Sb/Br)"
FID1 FID2 FID3: "Fiducial mark.  There is nothing to buy or mount."
GND1 GND2: "Test Point, Multipurpose, Black, TH"
J1 J2: "Terminal Block, 2.5mm, 3 Pos, TH"
J4 J5: "Connector, Receptacle, 100mil, 10x2, Gold plated, TH"
J6: "Header (shrouded), 100mil, 7x2, Gold, TH"
J7: "USB 2.0 TYPE B, R/A, SMT"
JP1 JP2 JP11 JP12 JP13 JP21 JP22 JP23 JP51 JP52: "Header, 2.54 mm, 2x1, Gold, TH"
JP31 JP32 JP53 JP61 JP62 JP63: "Header, 2.54 mm, 3x1, Gold, TH"
L1: "Coupled inductor,  A, 0.3 ohm, +/- 25%, SMD"
L2 L3: "Ferrite Bead, 600 ohm @ 100 MHz, 1 A, 0603"
LED1 LED2 LED3: "LED, Red, SMD"
Logo2: library part Pb-Free
Logo3: library part FCC_disclaimer, "FCC_disclaimer"
Logo4: library part TI_Logo, "Texas Instrument Corporate Signature"
R20 R203 R207: library part CRCW04021K00FKED, "RES, 1.00 k, 1%, 0.063 W, 0402"
R100: library part CRCW040251R0JNED, "RES, 51, 5%, 0.063 W, 0402"
R101 R111: library part CMF50150K00FHEB, "RES, 150 k, 1%, 0.25 W, TH"
R102 R112: library part CRCW0805100KFKEA, "RES, 100 k, 1%, 0.125 W, 0805"
R103 R113: library part CRCW0805200KFKEA, "RES, 200 k, 1%, 0.125 W, 0805"
R104 R105: library part CRCW04024K70JNED, "RES, 4.7 k, 5%, 0.063 W, 0402"
R106: library part CRCW04022K00FKED, "RES, 2.00 k, 1%, 0.063 W, 0402"
R200 R201: library part CRCW04022K70JNED, "RES, 2.7 k, 5%, 0.063 W, 0402"
R202: library part CRCW040247K0JNED, "RES, 47 k, 5%, 0.063 W, 0402"
R204 R206: library part CRCW040227R0JNED, "RES, 27, 5%, 0.063 W, 0402"
R205: library part CRCW04021K40FKED, "RES, 1.40 k, 1%, 0.063 W, 0402"
R208: library part CRCW06031M00FKEA, "RES, 1.00 M, 1%, 0.1 W, 0603"
R209: library part CRCW0402100RFKED, "RES, 100, 1%, 0.063 W, 0402"
S1 S2: "Switch, Tactile, SPST-NO, 0.05A, 12V, SMT"
S3 S4: library part TL1015AF160QG, "Switch, Tactile, SPST-NO, 0.05A, 12V, SMT"
U1: "Ultra Low Power Stereo Audio Codec With Embedded miniDSP, RHB0032E"
U2: "25 MHz Mixed Signal Microcontroller with 128 KB Flash, 8192 B SRAM and 63 GPIOs, -40 to 85 degC, 80-pin QFP (PN), Green (RoHS & no Sb/Br)"
U5: "Cap-Free, NMOS, 400mA Low-Dropout Regulator with Reverse Current Protection, DBV0005A"
U101: "Low-Offset, Rail-to-Rail I/O Operational Amplifier, DBV0005A"
U102: "Precision, Low Noise, Low Quiescent Current Operational Amplifier, 2 to 5.5 V, -40 to 125 degC, 8-pin SOP (DGK0008A), Green (RoHS & no Sb/Br)"
U103: "Precision, Low Noise, Low Iq Operational Amplifier, 2.2 to 5.5 V, -40 to 125 degC, 5-pin SOT23 (DCK0005A), Green (RoHS & no Sb/Br)"
U200: "IC, EEPROM, 512kB, 1MHz, SOIC-8"
Y101: "Crystal, 32.768kHz, 12.5pF, SMD"
Y102: "Crystal, 12.000MHz, 18pF, SMD"
ZZ2 ZZ3 ZZ4: library part AssemblyNote

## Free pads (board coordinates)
  round 125 hole 125 unplated: 1(100.8,100.94) 2(2758.28,100.94) 3(100.8,3152.13) 4(2758.28,3152.13)

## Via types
v1: diameter 23.62, hole 11.81, Top Layer to Bottom Layer, 200 vias
v2: diameter 23.62, hole 11.81, Top Layer to Bottom Layer, tented top, 2 vias
v3: diameter 23.62, hole 11.81, Top Layer to Bottom Layer, tented bottom, 1 vias

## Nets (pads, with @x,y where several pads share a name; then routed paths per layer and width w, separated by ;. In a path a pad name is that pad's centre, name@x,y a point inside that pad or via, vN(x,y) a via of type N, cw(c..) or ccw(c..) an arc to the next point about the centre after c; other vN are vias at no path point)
+3.3V_BP: C216.2 J4.1 JP52.1 | length 1185.9
  Top Layer w12: J4.1@2327.17,520.47 2327.16,439.5 C216.2@2329.14,437.52
  Bottom Layer w15: J4.1@2327.17,520.47 2736.5,520.47 2773,556.97 2773,1078.73 JP52.1@2688.58,1163.15
+3.3V_JTAG: J6.2 JP53.1 | length 1931.1
  Top Layer w15: J6.2@1631.58,242.52 v1(1631.58,378.42) ; JP53.1@2688.58,1043.07 2760.85,970.8 v1(2760.85,430.85)
  Bottom Layer w8: 2746.56,433.33 2758.37,433.33 v1(2760.85,430.85)
  Bottom Layer w15: v1(1631.58,378.42) 1686.5,433.33 2746.56,433.33
+3.3V_LDO: C22.2 JP51.1 U5.5 | length 944.9
  Top Layer w16: v1(2322.37,1872.52) 2468,1726.89 2468,1503.81 JP51.1@2688.58,1283.23 ; JP51.1@2689.77,1284.41 JP51.1@2690.95,1283.23
  Bottom Layer w12: C22.2@2163.47,1804.92 C22.2@2168.47,1804.92 ; C22.2@2167.37,1806.02 C22.2@2168.47,1804.92 ; U5.5@2228.24,1804.92 C22.2@2168.47,1804.92
  Bottom Layer w16: U5.5@2228.24,1804.92 2228.24,1828.39 2272.37,1872.52 v1(2322.37,1872.52)
+3.3V_SUPPLY: +3.3V.1 C100.2 C101.2 C108.2 C109.1 C110.1 C111.1 C113.1 C200.2 C209.1 C210.1 C211.1 C215.1 JP1.1 R104.1 R105.1 R200.2 R201.2 R202.2 R209.2 U1.6 U1.26 U2.11 U2.18 U2.50 U101.5 U102.8 U103.5 U200.1 U200.8 | length 3730.8
  Top Layer w8: C108.2@1145,1981.5 U1.26@1335.05,1981.5 ; C100.2@1459.06,1757.31 U1.6@1459.06,1837.8
  Top Layer w10: v1(435,2170) R209.2@435,2216.38 ; v1(1023.75,1023.9) C210.1@1057.37,1023.9 1080.36,1046.89 U2.50@1162.4,1046.89 ; U2.11@1691.93,1046.89 1756,1046.89 1845.37,957.52 C209.1@1922.37,957.52 v1(1922.37,922.52) ; U2.18@1691.93,1184.69 1768.16,1184.69 C211.1@1772.37,1188.9 ; R202.2@1921.54,575.87 1922.68,577 v1@1959,577
  Top Layer w12: C109.1@1145,2050 C109.1@1150,2055 v1(1205,2055) ; v1(1400,1720) 1425,1695 C101.2@1458.5,1695 1458.5,1756.76 C100.2@1459.06,1757.31 ; C211.1@1772.37,1188.9 1800.99,1217.52 C215.1@1842.37,1217.52 v1(1842.37,1172.52)
  Top Layer w16: v1(1036.21,1798.79) R104.1@1086.38,1798.79
  Top Layer w20: C108.2@1145,1981.5 C109.1@1145,2050
  +3.3V_Supply w20: 1205,1950 v1(1205,2055)
  +3.3V_Supply w30: 1299,1922.44 1299,2149 1420,2270 v1(1420,2685) ; v1(1510,2845) 1588,2845 1865,2568 1865,2270 1925,2210
  Bottom Layer w10: v3(814.89,1465) 828.75,1451.14 C200.2@852.37,1451.14 ; C200.2@852.37,1448.9 853.71,1450.24 U200.8@912.37,1450.24 ; v1(906.52,1382.52) R201.2@965.13,1382.52 ; U200.1@912.37,1664.8 v1(912.37,1722.52)
  Bottom Layer w12: R105.1@73,1610.62 v1(73,1659) ; R200.2@1130,1491.62 1168.38,1491.62 v1(1195,1465) ; U102.8@1379.97,2744.13 1379.97,2686.35 C110.1@1378.62,2685 v1(1420,2685) ; v1(1510,2845) C111.1@1556.38,2845 1558.08,2843.3 U103.5@1558.08,2793.11 ; U101.5@1949.13,2002.6 2003.78,2002.6 2005,2001.38 v1(2038,2001.38)
  other v1: 1962,577
+5V_BP: C217.2 J4.2 JP2.2 | length 526.9
  Top Layer w12: J4.2@2227.17,520.47 2227.16,436.46 C217.2@2228.62,435
  Bottom Layer w15: J4.2@2229.53,522.99 2279.06,572.52 2440.63,572.52 JP2.2@2588.58,720.47
+5V_USB: +5V.1 C23.2 C24.1 C212.2 D1.1 JP2.1 L3.2 U2.65 U5.1 U5.3 | length 4679.2
  Top Layer w12: +5V.1@1167.37,319 C212.2@1167.37,441.02 ; C212.2@1168.87,442.52 C212.2@1167.37,441.02 ; U2.65@1318.9,772.28 1318.9,639.05 1167.37,487.52 C212.2@1167.37,441.02
  Top Layer w15: L3.2@443.37,491.52 617.89,317 907.37,317 907.37,222.37 850,165 706.84,165 D1.1@659.53,212.31 ; C24.1@909.05,319 +5V.1@1167.37,319 ; v1(2345.75,317.81) 2526.46,317.81 2739.85,531.21 2739.85,669.21 JP2.1@2688.58,720.47 2417.37,991.69 v1(2417.37,1727.52)
  Bottom Layer w15: +5V.1@1177.57,317.81 v1(2345.75,317.81)
BP_ANALOG_IN_1: J4.3 U2.2 | length 831.6
  Top Layer w8: U2.2@1691.93,869.73 1790.16,869.73 v1(1817.37,842.52) ; v1(1963.47,616.6) 2151.45,616.6 2207.37,672.52 2275.12,672.52 J4.3@2327.17,620.47
  Bottom Layer w8: v1(1817.37,842.52) 1817.37,762.7 v1(1963.47,616.6)
BP_ANALOG_IN_2: J4.11 U2.3 | length 728
  Top Layer w8: U2.3@1691.93,889.41 1810.48,889.41 v1(1862.37,837.52) ; v1(2084.85,840) 2217.37,972.52 2279.21,972.52 J4.11@2327.17,1020.47
  Bottom Layer w8: v1@1865.89,840 v1(2084.85,840)
BP_ANALOG_IN_3: J4.6 U2.77 | length 784
  Top Layer w8: U2.77@1555.12,772.28 1555.12,719.77 1622.37,652.52 2159.06,652.52 J4.6@2229.53,722.99
BP_ANALOG_IN_4: J4.8 U2.78 | length 781.2
  Top Layer w8: U2.78@1574.8,772.28 1574.8,727.49 1629.77,672.52 2079.21,672.52 J4.8@2227.17,820.47
BP_ANALOG_IN_5: J4.10 U2.79 | length 781.7
  Top Layer w8: U2.79@1594.49,772.28 1594.49,735.4 1637.37,692.52 1999.21,692.52 J4.10@2227.17,920.47
BP_ANALOG_IN_6: J4.12 U2.80 | length 786
  Top Layer w8: U2.80@1614.17,772.28 1614.17,740.72 1644.09,710.8 1917.49,710.8 J4.12@2227.17,1020.47 ; J4.12@2228.78,1022.99 J4.12@2229.53,1022.99
BP_ANALOG_IN_7: J4.14 U2.1 | length 717.5
  Top Layer w8: U2.1@1691.93,850.04 1764.96,850.04 1805.1,809.9 1979.75,809.9 2182.37,1012.52 2182.37,1075.68 J4.14@2227.17,1120.47
BP_ANALOG_IN_8: J4.16 U2.4 | length 780.8
  Top Layer w8: U2.4@1691.93,909.1 1833.98,909.1 1884.08,859 1993.85,859 2157.37,1022.52 2157.37,1150.68 J4.16@2227.17,1220.47
BP_I2C_SCL: J4.17 U2.47 | length 1296.5
  Top Layer w8: U2.47@1162.4,1105.95 1219.66,1105.95 1267.23,1058.38 1623.38,1058.38 v1(1623.46,1058.3)
  Bottom Layer w8: v1(1623.46,1058.3) 1833.35,1268.19 2274.73,1268.19 J4.17@2329.53,1322.99
BP_I2C_SDA: J4.19 U2.46 | length 1323.9
  Top Layer w8: U2.46@1162.4,1125.63 1229.26,1125.63 1268.89,1086 v1@1545.75,1086
  Bottom Layer w8: v1(1545,1086) 1831.52,1372.52 2279.06,1372.52 J4.19@2329.53,1422.99
BP_IO_1: J4.9 U2.27 | length 1622.5
  Top Layer w8: U2.27@1496.06,1301.81 1496.06,1406.06 1606,1516 2317,1516 2390,1443 2390,983.31 J4.9@2327.17,920.47
BP_IO_2: J4.15 U2.25 | length 1136.3
  Top Layer w8: U2.25@1535.43,1301.81 1535.43,1395.43 1625.47,1485.47 2239.53,1485.47 2278,1447 2278,1269.64 J4.15@2327.17,1220.47
BP_IO_3: J5.20 U2.16 | length 1277.4
  Top Layer w8: J5.20@529.54,1422.99 580.53,1372 664,1372 716,1320 1124,1320 1298.68,1145.32 U2.16@1691.93,1145.32
BP_IO_4: J5.8 U2.55 | length 684.4
  Top Layer w8: J5.8@529.54,822.99 579.06,872.52 647.52,872.52 723.27,948.27 U2.55@1162.06,948.27
BP_IO_5: J5.19 U2.17 | length 1169.3
  Top Layer w8: J5.19@629.54,1422.99 1043.53,1422.99 1301.52,1165 U2.17@1691.93,1165
BP_IO_6: J5.17 U2.42 | length 582
  Top Layer w8: J5.17@629.54,1322.99 748.16,1204.37 U2.42@1162.4,1204.37
BP_IO_7: J5.15 U2.43 | length 548.7
  Top Layer w8: J5.15@629.54,1222.99 667.84,1184.69 U2.43@1162.4,1184.69
BP_IO_8: J5.13 U2.44 | length 553.7
  Top Layer w8: J5.13@627.17,1120.47 671.69,1165 U2.44@1162.4,1165
BP_IO_9: J4.18 U2.23 | length 779.1
  Top Layer w8: U2.23@1574.8,1301.81 1574.8,1369.95 1620.85,1416 2131.64,1416 J4.18@2227.17,1320.47
BP_IO_10: J4.20 U2.24 | length 808.6
  Top Layer w8: U2.24@1555.12,1301.81 1555.12,1385.27 1636.85,1467 2180.64,1467 J4.20@2227.17,1420.47
BP_PWM_OUT_1: J5.4 U2.29 | length 2192.2
  Top Layer w8: J5.4@529.54,622.99 422.37,730.16 422.37,1472.52 542.85,1593 1325,1593 1456.69,1461.31 U2.29@1456.69,1301.81
BP_PWM_OUT_2: J5.7 U2.56 | length 576.7
  Top Layer w8: J5.7@629.54,822.99 735.32,928.78 U2.56@1162.4,928.78
BP_PWM_OUT_3: J5.5 U2.57 | length 610
  Top Layer w8: J5.5@629.54,722.99 815.64,909.1 U2.57@1162.4,909.1
BP_PWM_OUT_4: J5.3 U2.58 | length 643.2
  Top Layer w8: J5.3@629.54,622.99 895.95,889.41 U2.58@1162.4,889.41
BP_PWM_OUT_5: J5.1 U2.59 | length 677.1
  Top Layer w8: J5.1@629.54,522.99 629.54,524.12 975.14,869.73 U2.59@1162.4,869.73
BP_SPI_CLK: J4.13 U2.45 | length 1296.5
  Top Layer w8: U2.45@1162.4,1145.32 1241.68,1145.32 1272,1115 v1(1350,1115)
  Bottom Layer w8: v1(1350,1115) 1434.32,1030.68 1750.84,1030.68 1897.44,1177.28 2270.36,1177.28 J4.13@2327.17,1120.47
BP_SPI_CS: J5.18 U2.48 | length 792.4
  Top Layer w8: v2(685,1135) 1054.89,1135 1103.63,1086.26 U2.48@1162.4,1086.26
  Bottom Layer w8: J5.18@529.54,1322.99 577.37,1275.16 649.84,1275.16 685,1240 v2(685,1135)
BP_SPI_CS_DISP: J5.16 U2.35 | length 1281.7
  Top Layer w8: J5.16@529.54,1222.99 472.37,1280.16 472.37,1447.52 517.47,1492.62 1266.44,1492.62 1338.58,1420.48 U2.35@1338.58,1301.81
BP_SPI_CS_W: J5.6 U2.31 | length 1971.1
  Top Layer w8: J5.6@529.54,722.99 447.37,805.16 447.37,1462.52 559.85,1575 1260,1575 1417.32,1417.68 U2.31@1417.32,1301.81
BP_SPI_MISO: J5.14 U2.52 | length 752.3
  Top Layer w8: v1(696.85,975.89) 1087.11,975.89 1118.74,1007.52 U2.52@1162.4,1007.52
  Bottom Layer w8: J5.14@529.54,1122.99 577.37,1075.16 577.37,997.63 599.11,975.89 v1(696.85,975.89)
BP_SPI_MOSI: J5.12 U2.51 | length 698
  Top Layer w8: J5.12@529.54,1022.99 579.06,1072.52 747.37,1072.52 823.89,996 1075.85,996 1107.06,1027.21 U2.51@1162.4,1027.21
BP_TC_1: J5.11 U2.33 | length 1442.2
  Top Layer w8: v1(710,1550) 1260.94,1550 1377.95,1432.98 U2.33@1377.95,1301.81 ; U2.33@1380.32,1304.33 U2.33@1380.37,1304.38
  Bottom Layer w8: J5.11@629.54,1022.99 687.84,1022.99 710,1045.15 v1(710,1550)
BP_TC_2: J5.9 U2.34 | length 1474.2
  Top Layer w8: v1@750,1520.52 1265.48,1520.52 1358.27,1427.73 U2.34@1358.27,1301.81
  Bottom Layer w8: J5.9@627.17,920.47 714.58,920.47 750,955.89 v1(750,1520)
BP_UART_RX: J4.5 U2.53 | length 1314.5
  Top Layer w8: U2.53@1162.4,987.84 1507.05,987.84 1712.89,782 v1(1850,782)
  Bottom Layer w8: v1(1850,782) 1954.48,677.52 2284.06,677.52 J4.5@2329.53,722.99
BP_UART_TX: J4.7 U2.54 | length 1284.1
  Top Layer w8: U2.54@1162.4,968.15 1496.74,968.15 1710.51,754.38 1909.38,754.38 v1(1926,771)
  Bottom Layer w8: v1(1926,771) 2277.54,771 J4.7@2329.53,822.99
CH1_IN_OPA: J1.2 R101.1 R102.1 R103.1 U102.3 | length 837.1
  Bottom Layer w8: R102.1@667.37,2692.52 R102.1@671.58,2696.73
  Bottom Layer w16: R102.1@667.37,2692.52 R103.1@817.37,2692.52 ; J1.2@711.58,2866.73 817.37,2760.95 R103.1@817.37,2692.52 ; U102.3@1204.77,2795.32 1069.32,2795.32 1069,2795 1064.85,2795 R101.1@922.37,2652.52 870,2652.52 830,2692.52 R103.1@817.37,2692.52
CH2_IN_OPA: J2.2 R111.1 R112.1 R113.1 U102.5 | length 1145.5
  Bottom Layer w16: U102.5@1379.97,2820.91 1469.09,2820.91 1505,2785 1505,2730 1582.48,2652.52 R111.1@1952.37,2652.52 1992.37,2692.52 R113.1@2057.37,2692.52 ; J2.2@2101.57,2866.73 2057.37,2822.53 R113.1@2057.37,2692.52 ; J2.2@2106.58,2861.73 J2.2@2111.58,2866.73 ; R112.1@2207.37,2692.52 R113.1@2057.37,2692.52
CH_VREF: J1.1 J2.1 JP31.2 U103.1 | length 2205.7
  Top Layer w16: J1.1@810.01,3063.58 982.37,2891.22 v1(982.37,2547.52) ; JP31.2@1353.16,2472.52 1459,2578.36 1459,2669 v1(1647.37,2857.37)
  Bottom Layer w16: v1(982.37,2547.52) 1057.37,2472.52 JP31.2@1353.16,2472.52 ; U103.1@1646.66,2793.11 1647.37,2793.82 v1(1647.37,2857.37) 1722.52,2932.52 2068.94,2932.52 J2.1@2200,3063.58 ; J2.1@2205,3058.58 J2.1@2210.01,3063.58
DSP_MCU_IO_1: IO1.1 U1.32 U2.21 | length 1134.2
  Top Layer w8: v1(1335.05,1800) U1.32@1335.05,1863.39 ; U2.21@1616.54,1304.33 1649.43,1304.33 v1(1649.71,1304.05)
  Bottom Layer w8: v1(1335.05,1800) 1775,1800 IO1.1@1835,1740 1835,1489.34 v1(1649.71,1304.05)
DSP_MCU_RST~: U1.31 U2.28 | length 724.8
  Top Layer w8: v1(1255,1785) 1255,1835 1303.07,1883.07 U1.31@1335.05,1883.07 ; v1(1384.76,1575.24) 1476.38,1483.62 U2.28@1476.38,1301.81
  Bottom Layer w8: v1(1255,1785) 1384.76,1655.24 v1(1384.76,1575.24)
DSP_SCL: JP61.2 U1.9 | length 1898.8
  Top Layer w8: JP61.2@265.75,1803.86 324.41,1862.52 712.37,1862.52 929.89,1645 1654,1645 1724,1715 1724,1776 1636.61,1863.39 U1.9@1524.02,1863.39
DSP_SDA: JP62.2 U1.10 | length 1919.9
  Top Layer w8: JP62.2@268.12,1683.78 321.86,1737.52 753.48,1737.52 863.48,1627.52 1672.94,1627.52 1743,1697.58 1743,1787 1646.93,1883.07 U1.10@1524.02,1883.07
